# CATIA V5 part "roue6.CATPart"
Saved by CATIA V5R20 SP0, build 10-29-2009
Part number: roue6
Bounding box of the stored display mesh (mm): x -325 to -290, y -951 to -919, z 0.01 to 31.99
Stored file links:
  D:\Dropbox\Pack 1 sylvain\mmoreau\mmoreau\mmoreau\fin\roue6.CATPart
  U:\think motion\fin\think motion2.CATProduct
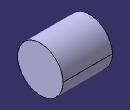
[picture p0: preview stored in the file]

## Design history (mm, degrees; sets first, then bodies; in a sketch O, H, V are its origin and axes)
Set1
  Plane1: linked copy from another document
  Point1: linked copy from another document
Body1 (main body)
  Sketch1 on Plane1, origin (-325, 0, 0), H (0, 1, 0), V (0, 0, 1)
    circle A1 centre (-935, 16) radius 16
    point P1 (-935, 16)
    reference projected point E1 (-935, 16) from Point1
    coincidence: P1 E1
    tangency: A1 H
  Pad1: profile Sketch1, direction (1, 0, 0), length 35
